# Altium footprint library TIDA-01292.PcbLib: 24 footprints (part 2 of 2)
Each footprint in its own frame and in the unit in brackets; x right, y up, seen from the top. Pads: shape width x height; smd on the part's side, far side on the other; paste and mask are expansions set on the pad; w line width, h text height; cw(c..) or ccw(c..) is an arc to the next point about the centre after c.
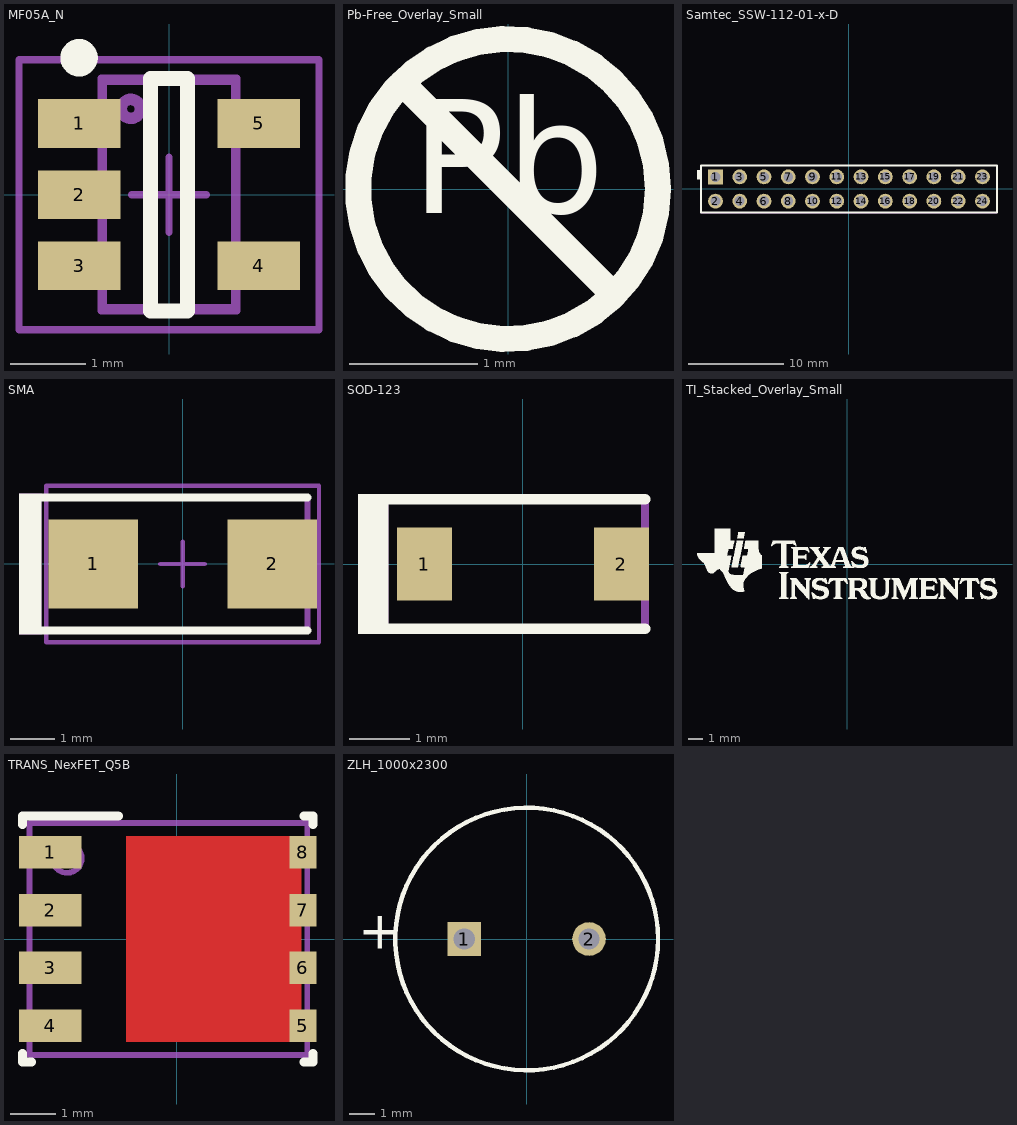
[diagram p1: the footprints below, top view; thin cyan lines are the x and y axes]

## MF05A_N [mm] "SOT23, 5-Leads, Body 2.9x1.6mm, Pitch 0.95mm, Lead Span 2.8mm, IPC Medium Density"
height 1.19
pads (5):
  rect 1.1x0.65 smd: 1(-1.2,0.95) 2(-1.2,0) 3(-1.2,-0.95) 4(1.2,-0.95) 5(1.2,0.95)
Top Overlay:
  circle w0.25: c-1.2,1.825 r0.125
  lines w0.2: -0.25,-1.55 -0.25,1.55 0.25,1.55 0.25,-1.55 -0.25,-1.55
Mechanical 5:
  circle w0.152: c-0.508,1.143 r0.127
  lines w0.127: -0.889,-1.524 -0.889,1.524 0.889,1.524 0.889,-1.524 -0.889,-1.524
  text ".Designator" at -0.457,0.508 h0.89
Mechanical 13:
  lines w0.1: -0.9,-1.55 0.9,-1.55 0.9,1.55 -0.9,1.55 -0.9,-1.55
Mechanical 15:
  lines w0.1: -0.5,0 0.5,0 ; 0,-0.5 0,0.5 ; -2,-1.8 2,-1.8 2,1.8 -2,1.8 -2,-1.8
3D body: height 1.19, standoff 0, extent -0.9,-1.55 0.9,1.55

## Pb-Free_Overlay_Small [mm]
height 8.64
Top Overlay:
  circle w0.203: c0,0 r1.168
  lines w0.203: -0.826,0.826 0.826,-0.826
  text "Pb" at -0.752,-0.48 h1.52

## Samtec_SSW-112-01-x-D [mm] "Receptacle, 12x2, 2.54mm, TH"
height 8.64
pads (24):
  rect 1.55x1.55 hole 1.04: 1(-13.97,1.27)
  round 1.55 hole 1.04: 2(-13.97,-1.27) 3(-11.43,1.27) 4(-11.43,-1.27) 5(-8.89,1.27) 6(-8.89,-1.27) 7(-6.35,1.27) 8(-6.35,-1.27) 9(-3.81,1.27) 10(-3.81,-1.27) 11(-1.27,1.27) 12(-1.27,-1.27) 13(1.27,1.27) 14(1.27,-1.27) 15(3.81,1.27) 16(3.81,-1.27) 17(6.35,1.27) 18(6.35,-1.27) 19(8.89,1.27) 20(8.89,-1.27) 21(11.43,1.27) 22(11.43,-1.27) 23(13.97,1.27) 24(13.97,-1.27)
Top Overlay:
  rectangle: -15.9,1 -15.5,2
  lines w0.2: -15.494,-2.477 15.494,-2.477 15.494,2.476 -15.494,2.476 -15.494,-2.477
Mechanical 5:
  lines w0.1: -15.494,-2.477 -15.494,2.476 15.494,2.476 15.494,-2.477 -15.494,-2.477
  text ".Designator" at -0.404,1.227 h0.89
3D body: height 8.51, standoff -2.64, extent -15.494,-2.477 15.494,2.476

## SMA [mm] "Molded Diode, 2-Leads, Body 4.3x2.6mm, IPC Medium Density, based on OnSemi component dimensions and land pattern"
height 2.27
pads (2):
  rect 2x2 smd: 1(-2,0) 2(2,0)
Top Overlay:
  rectangle: -3.658,-1.575 -3.15,1.575
  lines w0.178: -3.327,-1.486 2.794,-1.486 ; -3.327,1.486 2.794,1.486
Mechanical 5:
  rectangle: -3.658,-1.575 -3.15,1.575
  lines w0.127: -3.327,-1.486 2.794,-1.486 2.794,1.486 -3.327,1.486
  text ".Designator" at -0.787,1.118 h0.89
Mechanical 15:
  lines w0.1: -0.5,0 0.5,0 ; 0,-0.5 0,0.5 ; -3.05,-1.75 3.05,-1.75 3.05,1.75 -3.05,1.75 -3.05,-1.75
3D body: height 2.42, standoff 0.02, extent -2.6,-1.3 2.6,1.3

## SOD-123 [mm] "On Semi recommended land pattern"
height 1.35
pads (2):
  rect 0.915x1.22 smd: 1(-1.637,0) 2(1.637,0)
Top Overlay:
  rectangle: -2.743,-1.168 -2.235,1.168
  lines w0.178: -2.413,-1.079 2.032,-1.079 ; -2.413,1.079 2.032,1.079
Mechanical 5:
  rectangle: -2.743,-1.168 -2.235,1.168
  lines w0.127: -2.413,-1.079 2.032,-1.079 2.032,1.079 -2.413,1.079
  text ".Designator" at -0.813,-0.33 h0.76
3D body: height 1.35, standoff 0, extent -1.932,-0.9 1.932,0.9

## TI_Stacked_Overlay_Small [mm]
height 8.64
Top Overlay:
  drawing of 18 lines, arcs and shapes, not listed

## TRANS_NexFET_Q5B [mm] "TI recommended land pattern (nominal) November 2012"
height 1.05
pads (8):
  rect 1.372x0.71 smd paste-0.4: 1(-2.776,1.905) 2(-2.776,0.635) 3(-2.776,-0.635) 4(-2.776,-1.905)
  rect 0.59x0.71 smd paste-0.3: 5(2.776,-1.905) 6(2.776,-0.635) 7(2.776,0.635) 8(2.776,1.905)
Top Layer:
  rectangle: -1.106,-2.26 2.744,2.26
Top Overlay:
  lines w0.2: -3.385,-2.52 -3.385,-2.7 -3.185,-2.7 ; -3.385,2.52 -3.385,2.7 -1.28,2.7 ; 2.8,-2.7 3,-2.7 3,-2.52 ; 2.8,2.7 3,2.7 3,2.52
Top Paste:
  rectangle: 0.723,0.15 2.017,0.896
  region: 0.373,0.896 -0.921,0.896 -0.921,0.15 0.373,0.15
  region: 0.373,-0.15 -0.921,-0.15 -0.921,-0.896 0.373,-0.896
  rectangle: 0.723,-0.896 2.017,-0.15
  region: 0.373,1.942 -0.921,1.942 -0.921,1.196 0.373,1.196
  rectangle: 0.723,1.196 2.017,1.942
  region: 0.373,-1.196 -0.921,-1.196 -0.921,-1.942 0.373,-1.942
  rectangle: 0.723,-1.942 2.017,-1.196
  rectangle: -3.312,1.624 -2.24,2.186
  rectangle: -3.312,0.354 -2.24,0.916
  rectangle: -3.312,-0.916 -2.24,-0.354
  rectangle: -3.312,-2.186 -2.24,-1.624
  rectangle: 2.303,1.651 3.069,2.159
  rectangle: 2.303,0.381 3.069,0.889
  rectangle: 2.303,-0.889 3.069,-0.381
  rectangle: 2.303,-2.159 3.069,-1.651
Mechanical 5:
  circle w0.127: c-2.405,1.775 r0.32
  lines w0.127: -3.23,-2.55 -3.23,2.55 2.875,2.55 2.875,-2.55 -3.23,-2.55
  text ".Designator" at -1.016,0.762 h0.89
3D body: height 1.05, standoff 0, extent -3.229,-2.549 2.874,2.549
3D body: height 1.06, standoff 1, extent -2.731,1.449 -2.079,2.101

## ZLH_1000x2300 [mm] "TH, 2-Leads, Dia 10mm, Pin Spacing 5mm"
height 25
pads (2):
  rect 1.35x1.35 hole 0.85: 1(-2.5,0)
  round 1.35 hole 0.85: 2(2.5,0)
Top Overlay:
  circle w0.18: c0,0 r5.263
  text "+" at -6.756,-0.381 h1.52
Mechanical 5:
  circle w0.1: c0,0 r5.25
  text "+" at -6.8,-0.8 h1.52
  text ".Designator" at -1.7,-0.4 h0.89
3D body: height 25.01, standoff -4, extent -5.209,-5.241 5.24,5.242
